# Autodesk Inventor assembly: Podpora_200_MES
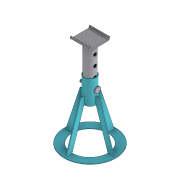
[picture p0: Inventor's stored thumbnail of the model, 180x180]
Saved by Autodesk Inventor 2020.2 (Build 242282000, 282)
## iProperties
Created: 2011-11
Part Number: Podpora_200_MES
Document SubType Name: Assembly
Designer: F.Stasiak
Catalog Web Link: www.expertbooks.pl
Manager: www.cadconsulting.pl
Company: Fabian Stasiak CAD Consulting
Author: F.Stasiak
Subject: Zbiór ćwiczeń. Autodesk Inventor 2020. Kurs Professional
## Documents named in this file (4)
- C:\2020_Kurs_Professional\R4 MES\Podpora\Podpora_200_MES.iam
- C:\2020_Kurs_Professional\R4 MES\Podpora\Stopa.iam
- C:\2020_Kurs_Professional\R4 MES\Podpora\Dźwigar.iam
- C:\2020_Kurs_Professional\R4 MES\Podpora\Trzczpień.ipt
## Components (3 placed, 3 different names)
1. Stopa:1 [sub-assembly] — Zestawiający:1, Zestawiający:3, Styczny:4
2. Dźwigar:1 [sub-assembly] — Zestawiający:1, Zestawiający:2, Styczny:3
3. Trzczpień:1 — Zestawiający:2, Zestawiający:3, Styczny:3, Styczny:4
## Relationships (5: Mate 3, Tangent 2)
- Zestawiający:1 [Mate]: Stopa:1 ↔ Dźwigar:1
- Zestawiający:2 [Mate]: Dźwigar:1 ↔ Trzczpień:1
- Zestawiający:3 [Mate]: Stopa:1 ↔ Trzczpień:1
- Styczny:3 [Tangent]: Dźwigar:1 ↔ Trzczpień:1
- Styczny:4 [Tangent]: Stopa:1 ↔ Trzczpień:1
## Named parameters: sa_0 = 0, sa_1 = 0, sa_2 = -3500000 mm
